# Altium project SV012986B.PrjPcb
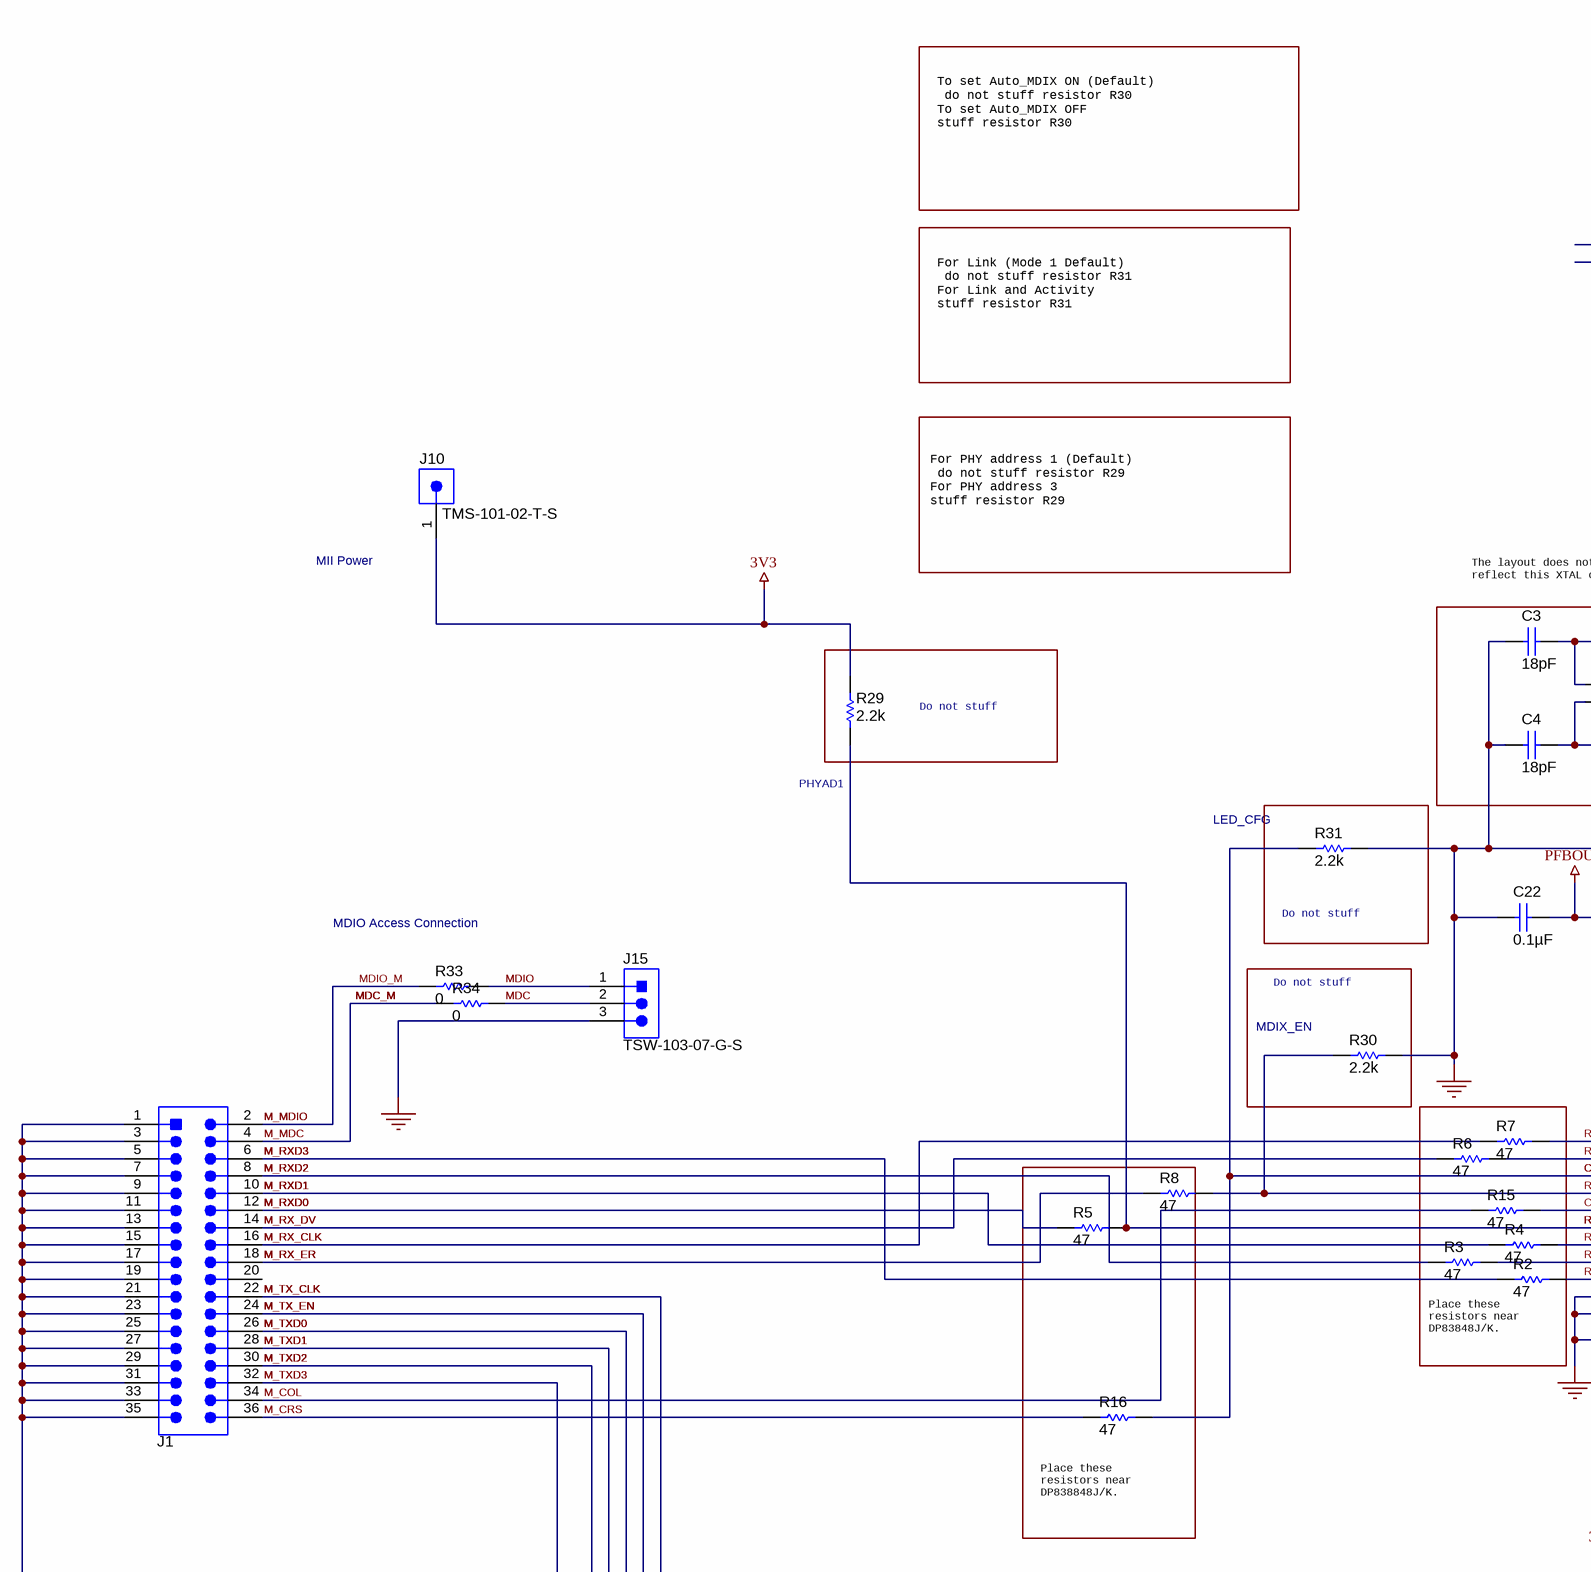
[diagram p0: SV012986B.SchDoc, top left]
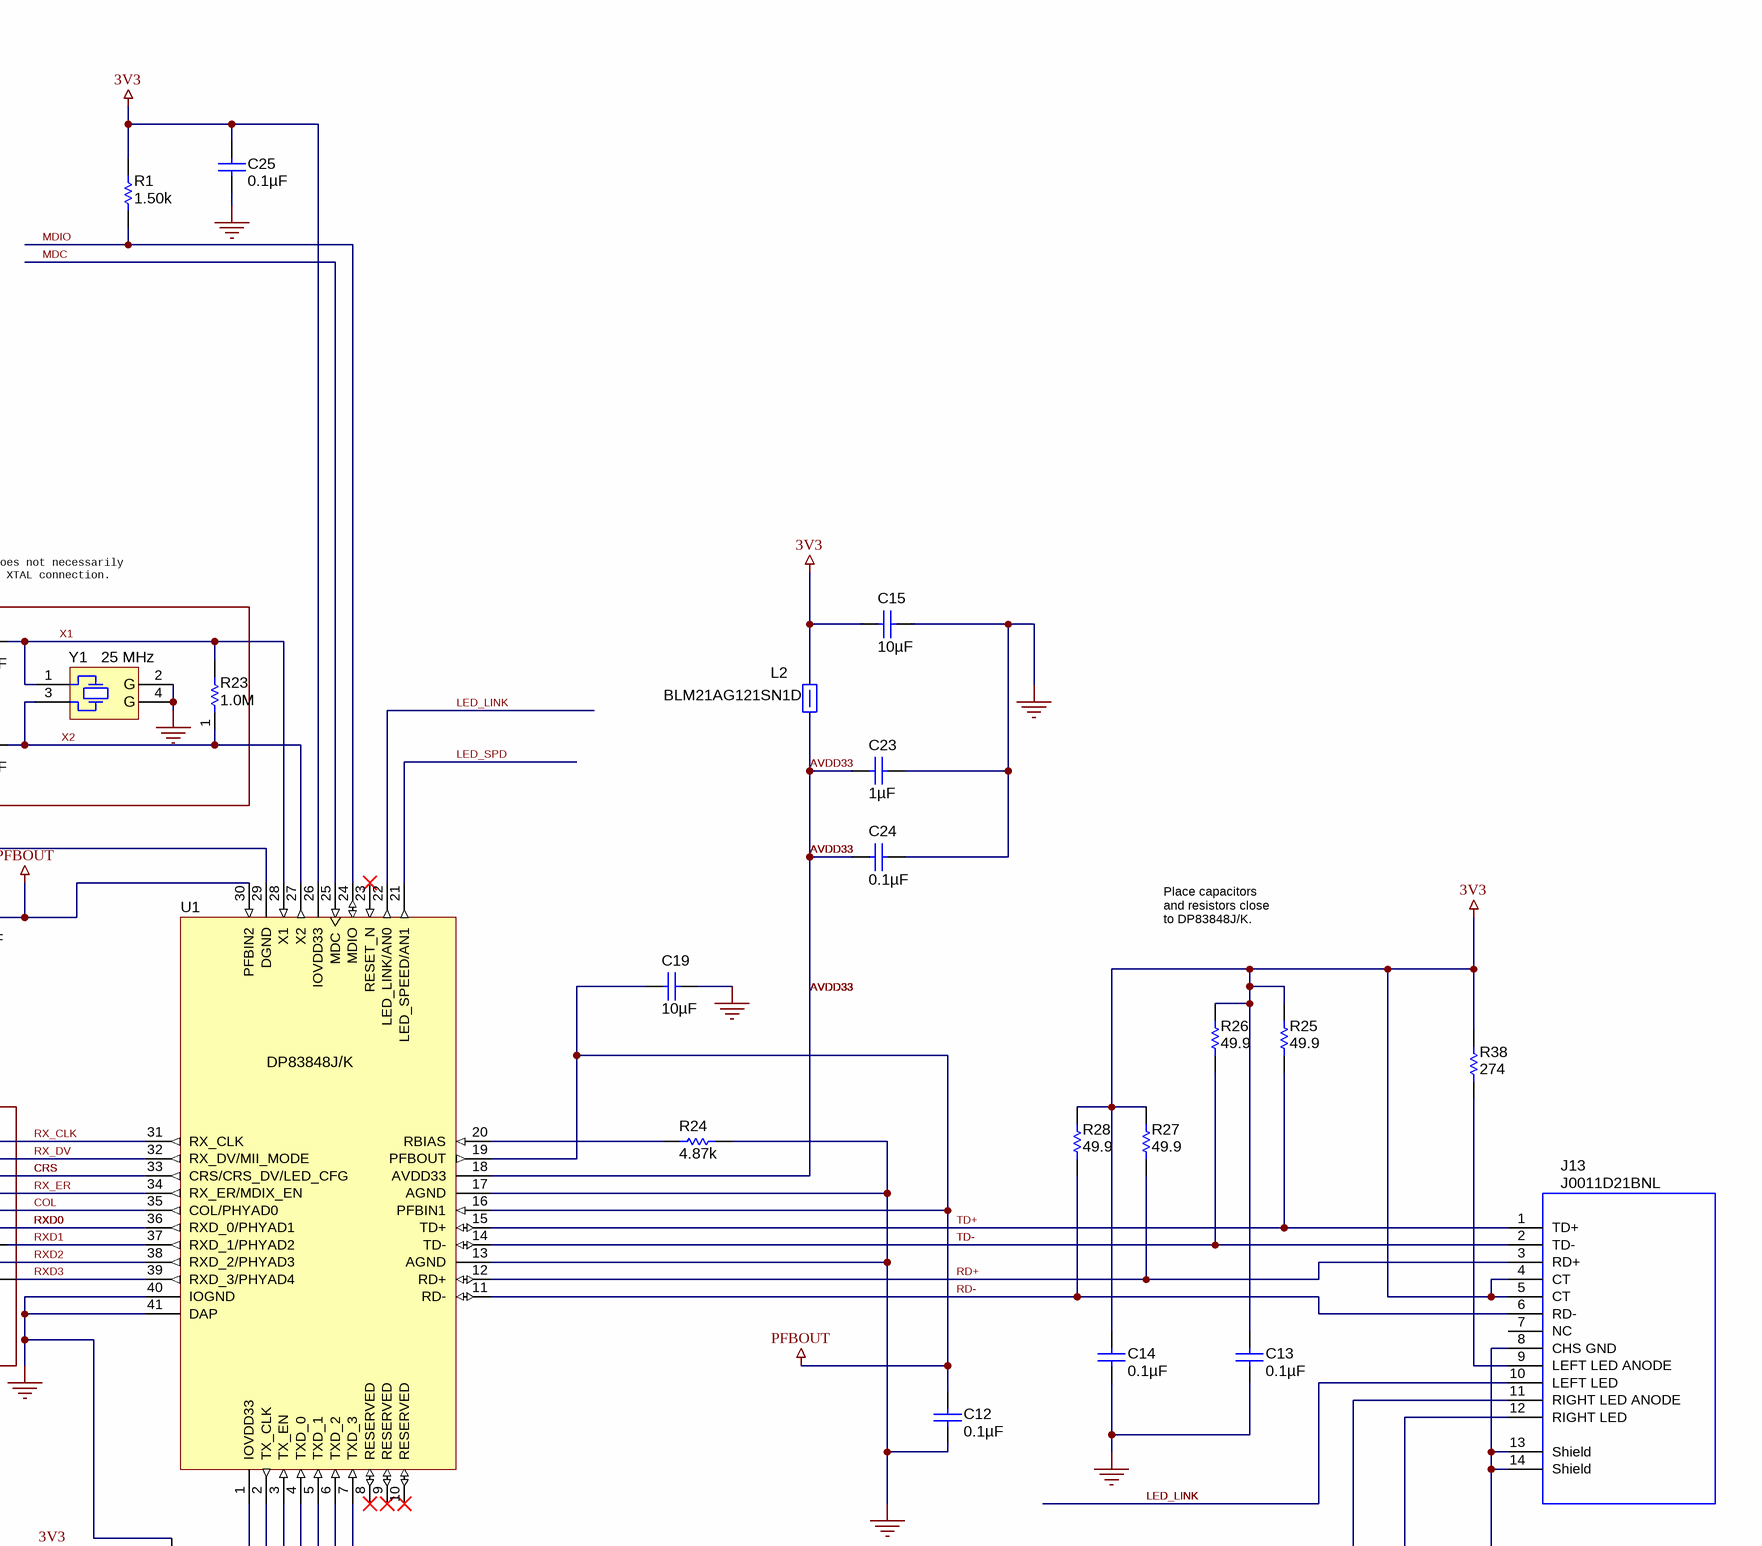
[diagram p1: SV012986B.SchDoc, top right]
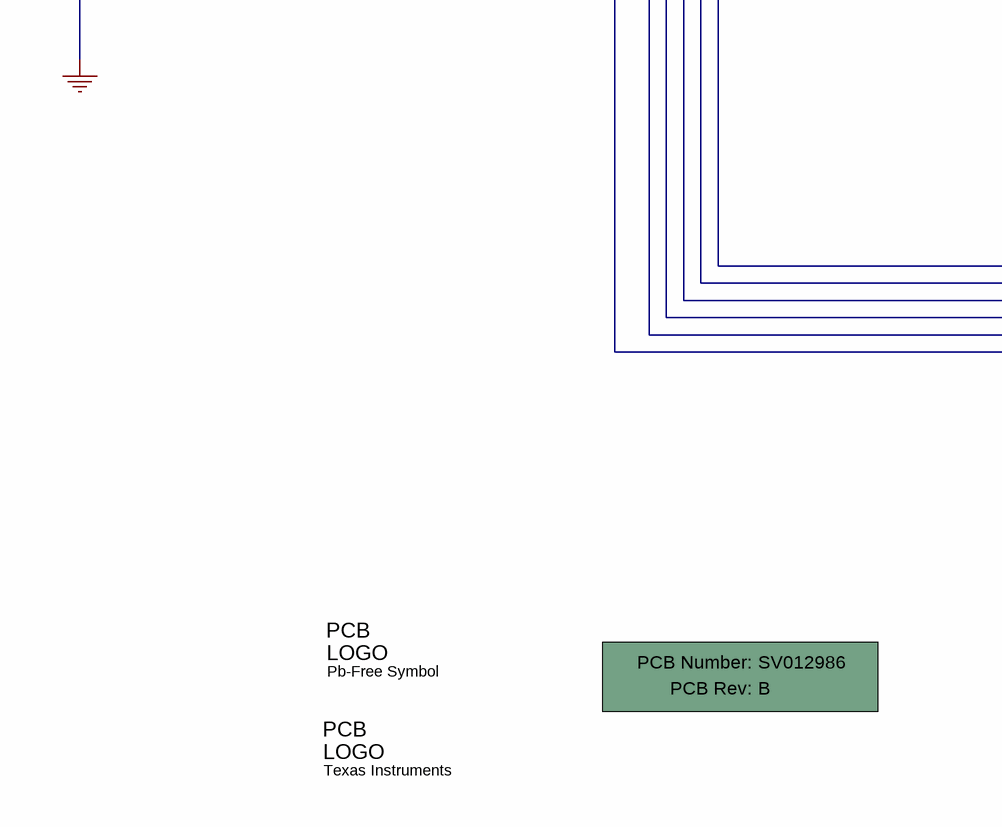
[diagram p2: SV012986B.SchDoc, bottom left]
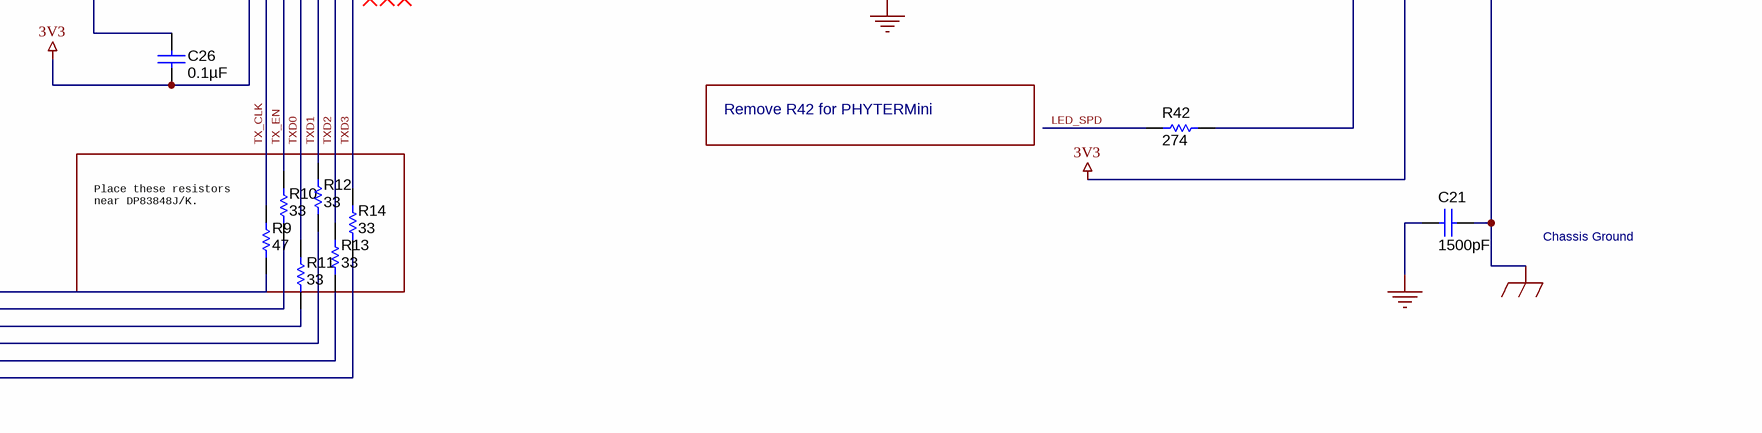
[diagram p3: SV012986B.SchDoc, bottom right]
CopyrightYear: 2014; EVM_Orderable: DP83848K-MAU-EK; PCB_Layout: SVTronics; PCB_Rev: B; PRJ_Customer: Public Release; PRJ_Engineer: Matt Dillingham; PRJ_Number: SV012986; PRJ_Title: DP83848K-MAU-EK; SCH_Rev: B; TechSupport: http://www.ti.com/support; TID: n/a
1 sheet, 52 parts. Net scope: global (net labels, ports and power ports of the same name join across sheets).
Board file: SV012986B.PCBDOC

## Sheet SV012986B.SchDoc
size 558 x 431 mm; Date: Not shown in title block; ApprovedBy: Not shown in title block; CheckedBy: Not shown in title block; Author: Not shown in title block; CompanyName: Not shown in title block; Engineer: Not shown in title block; Organization: Not shown in title block; Address1: Not shown in title block; Address2: Not shown in title block; Address3: Not shown in title block; Address4: Not shown in title block; DocumentNumber: 1; Revision: Use project parameter SCH_Rev; SheetNumber: 2; SheetTotal: 3; PageSetup: Record=PageOptions¦CenterHorizontal=True¦CenterVertical=True¦PrintScale=1.00¦XCorrection=1.00¦YCorrection=1.00¦PrintKind=0¦BorderSize=5000000¦LeftOffset=0¦BottomOffset=0¦Orientation=2¦PaperLength=1000¦PaperWidth=1000¦Scale=100¦PaperSource=15¦PrintQuality=600¦MediaType=1¦DitherType=10¦PaperKind=Letter¦PrintScaleMode=1

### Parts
!PCB  Printed Circuit Board  (value not drawn)  (mechanical)
C3  ValueDisplayed: 18pF  [0603]  (hidden comment: GRM1885C1H180JA01D)
C4  ValueDisplayed: 18pF  [0603]  (hidden comment: GRM1885C1H180JA01D)
C12  ValueDisplayed: 0.1µF  [0603]  (hidden comment: GRM188R61C104KA01D)
C13  ValueDisplayed: 0.1µF  [0603]  (hidden comment: GRM188R61C104KA01D)
C14  ValueDisplayed: 0.1µF  [0603]  (hidden comment: GRM188R61C104KA01D)
C15  ValueDisplayed: 10µF  [0805L]  (hidden comment: C0805C106M8PACTU)
C19  ValueDisplayed: 10µF  [0805_HV]  (hidden comment: C0805C106M8PACTU)
C21  ValueDisplayed: 1500pF  [1808]  (hidden comment: GR442QR73D152KW01L)
C22  ValueDisplayed: 0.1µF  [0603]  (hidden comment: GRM188R61C104KA01D)
C23  ValueDisplayed: 1µF  [0805_HV]  (hidden comment: GRM216R61A105KA01D)
C24  ValueDisplayed: 0.1µF  [0603]  (hidden comment: GRM188R61C104KA01D)
C25  ValueDisplayed: 0.1µF  [0603]  (hidden comment: GRM188R61C104KA01D)
C26  ValueDisplayed: 0.1µF  [0603]  (hidden comment: GRM188R61C104KA01D)
J1  TSW-118-07-G-D  [TSW-118-07-G-D]  (value not drawn)
J10  TMS-101-02-T-S  [SAMTEC_TMS-101-02-T-S]
J13  J0011D21BNL  [Pulse_J0011D21BNL]
J15  TSW-103-07-G-S  [TSW-103-07-G-S]
L2  BLM21AG121SN1D  [0805_HV]
Logo1  Pb-Free Symbol  [Pb-Free_Overlay_Small]  (no BOM)
Logo2  Texas Instruments  [TI_Symbol_Overlay_Small]  (no BOM)
R1  ValueDisplayed: 1.50k  [0402L]  (hidden comment: CRCW04021K50FKED)
R2  ValueDisplayed: 47  [0402]  (hidden comment: CRCW040247R0JNED)
R3  ValueDisplayed: 47  [0402]  (hidden comment: CRCW040247R0JNED)
R4  ValueDisplayed: 47  [0402]  (hidden comment: CRCW040247R0JNED)
R5  ValueDisplayed: 47  [0402L]  (hidden comment: CRCW040247R0JNED)
R6  ValueDisplayed: 47  [0402]  (hidden comment: CRCW040247R0JNED)
R7  ValueDisplayed: 47  [0402]  (hidden comment: CRCW040247R0JNED)
R8  ValueDisplayed: 47  [0402L]  (hidden comment: CRCW040247R0JNED)
R9  ValueDisplayed: 47  [0402]  (hidden comment: CRCW040247R0JNED)
R10  ValueDisplayed: 33  [0402]  (hidden comment: CRCW040233R0JNED)
R11  ValueDisplayed: 33  [0402L]  (hidden comment: CRCW040233R0JNED)
R12  ValueDisplayed: 33  [0402]  (hidden comment: CRCW040233R0JNED)
R13  ValueDisplayed: 33  [0402]  (hidden comment: CRCW040233R0JNED)
R14  ValueDisplayed: 33  [0402]  (hidden comment: CRCW040233R0JNED)
R15  ValueDisplayed: 47  [0402]  (hidden comment: CRCW040247R0JNED)
R16  ValueDisplayed: 47  [0402]  (hidden comment: CRCW040247R0JNED)
R23  ValueDisplayed: 1.0M  [0402]  (hidden comment: CRCW04021M00JNED)
R24  ValueDisplayed: 4.87k  [0402L]  (hidden comment: CRCW04024K87FKED)
R25  ValueDisplayed: 49.9  [0603]  (hidden comment: CRCW060349R9FKEA)
R26  ValueDisplayed: 49.9  [0603]  (hidden comment: CRCW060349R9FKEA)
R27  ValueDisplayed: 49.9  [0603]  (hidden comment: CRCW060349R9FKEA)
R28  ValueDisplayed: 49.9  [0603]  (hidden comment: CRCW060349R9FKEA)
R29  ValueDisplayed: 2.2k  [0402L]  (hidden comment: CRCW04022K20JNED)
R30  ValueDisplayed: 2.2k  [0402L]  (hidden comment: CRCW04022K20JNED)
R31  ValueDisplayed: 2.2k  [0402]  (hidden comment: CRCW04022K20JNED)
R33  ValueDisplayed: 0  [0402]  (hidden comment: CRCW04020000Z0ED)
R34  ValueDisplayed: 0  [0402]  (hidden comment: CRCW04020000Z0ED)
R38  ValueDisplayed: 274  [0402]  (hidden comment: CRCW0402274RFKED)
R42  ValueDisplayed: 274  [0402S]  (hidden comment: CRCW0402274RFKED)
U1  DP83848J/K  [SQA40B]
Y1  Frequency: 25 MHz  [Ecliptek_EA5070]  (hidden comment: EA5070PA18-25.000M)

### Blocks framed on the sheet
Do not stuff: R29
Do not stuff: R31
MDIX_EN: R30

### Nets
3V3: C13.1 C14.1 C15.2 C25.1 C26.2 J10.1 J13.4(CT) J13.5(CT) J13.12(RIGHT_LED) L2.2 R1.2 R25.2 R26.2 R27.2 R28.2 R29.2 R38.2 U1.1(IOVDD33) U1.26(IOVDD33)
GND: C3.2 C4.2 C12.2 C13.2 C14.2 C15.1 C19.1 C21.2 C22.2 C23.1 C24.1 C25.2 C26.1 J1.1 J1.3 J1.5 J1.7 J1.9 J1.11 J1.13 J1.15 J1.17 J1.19 J1.21 J1.23 J1.25 J1.27 J1.29 J1.31 J1.33 J1.35 J15.3 R24.2 R30.1 R31.2 U1.13(AGND) U1.17(AGND) U1.29(DGND) U1.40(IOGND) U1.41(DAP) Y1.2(GND) Y1.4(GND)
GND_Chassis: C21.1 J13.8(CHS_GND) J13.13(Shield) J13.14(Shield)
PFBOUT: C12.1 C19.2 C22.1 U1.16(PFBIN1) U1.19(PFBOUT) U1.30(PFBIN2)
AVDD33: C23.2 C24.2 L2.1 U1.18(AVDD33)
COL: R15.2 U1.35(COL/PHYAD0)
CRS: R16.2 R31.1 U1.33(CRS/CRS_DV/LED_CFG)
LED_LINK: J13.10(LEFT_LED) U1.22(LED_LINK/AN0)
LED_SPD: R42.1 U1.21(LED_SPEED/AN1)
M_COL: J1.34 R15.1
M_CRS: J1.36 R16.1
M_MDC: J1.4 R34.1  [also labelled MDC_M]
M_MDIO: J1.2 R33.1  [also labelled MDIO_M]
M_RX_CLK: J1.16 R7.1
M_RX_DV: J1.14 R6.1
M_RX_ER: J1.18 R8.1
M_RXD0: J1.12 R5.1
M_RXD1: J1.10 R4.1
M_RXD2: J1.8 R3.1
M_RXD3: J1.6 R2.1
M_TX_CLK: J1.22 R9.1
M_TX_EN: J1.24 R10.1
M_TXD0: J1.26 R11.1
M_TXD1: J1.28 R12.1
M_TXD2: J1.30 R13.1
M_TXD3: J1.32 R14.1
MDC: J15.2 R34.2 U1.25(MDC)
MDIO: J15.1 R1.1 R33.2 U1.24(MDIO)
RD+: J13.3(RD+) R27.1 U1.12(RD+)
RD-: J13.6(RD-) R28.1 U1.11(RD-)
RX_CLK: R7.2 U1.31(RX_CLK)
RX_DV: R6.2 U1.32(RX_DV/MII_MODE)
RX_ER: R8.2 R30.2 U1.34(RX_ER/MDIX_EN)
RXD0: R5.2 R29.1 U1.36(RXD_0/PHYAD1)
RXD1: R4.2 U1.37(RXD_1/PHYAD2)
RXD2: R3.2 U1.38(RXD_2/PHYAD3)
RXD3: R2.2 U1.39(RXD_3/PHYAD4)
TD+: J13.1(TD+) R25.1 U1.15(TD+)
TD-: J13.2(TD-) R26.1 U1.14(TD-)
TX_CLK: R9.2 U1.2(TX_CLK)
TX_EN: R10.2 U1.3(TX_EN)
TXD0: R11.2 U1.4(TXD_0)
TXD1: R12.2 U1.5(TXD_1)
TXD2: R13.2 U1.6(TXD_2)
TXD3: R14.2 U1.7(TXD_3)
X1: C3.1 R23.2 U1.28(X1) Y1.1
X2: C4.1 R23.1 U1.27(X2) Y1.3
NetJ13_9: J13.9(LEFT_LED_ANODE) R38.1
NetJ13_11: J13.11(RIGHT_LED_ANODE) R42.2
NetR24_1: R24.1 U1.20(RBIAS)

Not connected (* = marked no-connect by the designer): J1 20; J13 7(NC); U1 8(RESERVED)* 9(RESERVED)* 10(RESERVED)* 23(RESET_N)*

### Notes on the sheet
- To set Auto_MDIX ON (Default)
  do not stuff resistor R30
  To set Auto_MDIX OFF
  stuff resistor R30
- For Link (Mode 1 Default)
  do not stuff resistor R31
  For Link and Activity
  stuff resistor R31
- MII Power
- For PHY address 1 (Default)
  do not stuff resistor R29
  For PHY address 3
  stuff resistor R29
- (near C3) The layout does not necessarily
  reflect this XTAL connection.
- (near R29) PHYAD1
- (near R31) LED_CFG
- MDIO Access Connection
- (near R30) Do not stuff
- Place capacitors
  and resistors close
  to DP83848J/K.
- (near R2) Place these
  resistors near
  DP83848J/K.
- (near R16) Place these
  resistors near
  DP838848J/K.
- Remove R42 for PHYTERMini
- Place these resistors
  near DP83848J/K.
- Chassis Ground

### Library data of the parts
!PCB = PCB: Manufacturer: Any; PartNumber: SV012986; SymbolCreator: a0412235
C3 C4 = GRM1885C1H180JA01D: CAP, CERM, 18 pF, 50 V, +/- 5%, C0G/NP0, 0603; Manufacturer: MuRata; Polarized: N; CompType: Capacitor; Value: 18pF; U/M: EA; Cap_F: 0.000000000018; Tolerance_%: 5; Value1: Unknown; VDC_V: 50; Value2: 50V; TaMin_C: -55; TaMax_C: 125
C12-C14 C22 C24-C26 = GRM188R61C104KA01D: CAP, CERM, 0.1 µF, 16 V, +/- 10%, X5R, 0603; Manufacturer: MuRata; Polarized: N; CompType: Capacitor; Value: 0.1uF; U/M: EA; Cap_F: 0.0000001; Tolerance_%: 10; Value1: Unknown; VDC_V: 16; Value2: 16V; TaMin_C: -55; TaMax_C: 85
C15 C19 = C0805C106M8PACTU: CAP, CERM, 10 µF, 10 V, +/- 20%, X5R, 0805; Manufacturer: Kemet; Polarized: N; CompType: Capacitor; Value: 10uF; U/M: EA; Cap_F: 0.00001; Tolerance_%: 20; ESR_ohm: 0.003; Value1: 0.003 ohm; VDC_V: 10; Value2: 10V; IRMS_A: 11.43; TaMin_C: -55; TaMax_C: 85; Cap_Case: 0805
C21 = GR442QR73D152KW01L: CAP, CERM, 1500 pF, 2000 V, +/- 10%, X7R, 1808; Manufacturer: MuRata; Polarized: N; CompType: Capacitor; Value: 1500pF; U/M: EA; Cap_F: 0.0000000015; Tolerance_%: 10; Value1: Unknown; VDC_V: 2000; Value2: 2000V; TaMin_C: -55; TaMax_C: 125
C23 = GRM216R61A105KA01D: CAP, CERM, 1 µF, 10 V, +/- 10%, X5R, 0805; Manufacturer: MuRata; Polarized: N; CompType: Capacitor; Value: 1uF; U/M: EA; Cap_F: 0.000001; Tolerance_%: 10; Value1: Unknown; Value2: 10V; TaMin_C: -55; TaMax_C: 85; Cap_Case: 0805
J1 = TSW-118-07-G-D: Header, 100mil, 18x2, Gold, TH; Manufacturer: Samtec; SymbolCreator: a0411947; U/M: EA
J10 = TMS-101-02-T-S: Header, 1x1, Tin, TH; Manufacturer: Samtec; SymbolCreator: a0412235; U/M: EA
J13 = J0011D21BNL: Connector, RJ-45 with integrated magnetics, 1x1, Gold, R/A, TH; Manufacturer: Pulse Engineering; SymbolCreator: Altium; U/M: EA
J15 = TSW-103-07-G-S: Header, 100mil, 3x1, Gold, TH; Manufacturer: Samtec; SymbolCreator: a0799628; U/M: EA
L2 = BLM21AG121SN1D: Ferrite Bead, 120 ohm @ 100 MHz, 0.8 A, 0805; Manufacturer: MuRata; Value: 120 ohm; Imax_A: 0.8; DCR_ohm: 0.1; Value1: 0.1 ohm; Value2: 0.8A; ZTyp@100MHz_Ohm: 120
Logo1 = Pb-Free: SymbolCreator: a0412235
Logo2 = TI_Logo: Texas Instrument Corporate Signature; SymbolCreator: a0412235
R1 = CRCW04021K50FKED: RES, 1.50 k, 1%, 0.063 W, 0402; Manufacturer: Vishay-Dale; CompType: Resistor; Value: 1.50k; Res_ohm: 1500; Value_Code: 1k50; Tolerance_%: 1; Power_W: 0.063; Value2: 0.063W; VDC_V: 50; TempCo: 100 ppm/C; EIA_Code: E96; U/M: EA
R2-R9 R15 R16 = CRCW040247R0JNED: RES, 47, 5%, 0.063 W, 0402; Manufacturer: Vishay-Dale; CompType: Resistor; Value: 47; Value_Code: 47R0; Tolerance_%: 5; Power_W: 0.063; Value2: 0.063W; VDC_V: 50; TempCo: 200 ppm/C; EIA_Code: E24; U/M: EA
R10-R14 = CRCW040233R0JNED: RES, 33, 5%, 0.063 W, 0402; Manufacturer: Vishay-Dale; CompType: Resistor; Value: 33; Value_Code: 33R0; Tolerance_%: 5; Power_W: 0.063; Value2: 0.063W; VDC_V: 50; TempCo: 200 ppm/C; EIA_Code: E24; U/M: EA
R23 = CRCW04021M00JNED: RES, 1.0 M, 5%, 0.063 W, 0402; Manufacturer: Vishay-Dale; CompType: Resistor; Value: 1.0Meg; Res_ohm: 1000000; Value_Code: 1M00; Tolerance_%: 5; Power_W: 0.063; Value2: 0.063W; VDC_V: 50; TempCo: 200 ppm/C; EIA_Code: E24; U/M: EA
R24 = CRCW04024K87FKED: RES, 4.87 k, 1%, 0.063 W, 0402; Manufacturer: Vishay-Dale; CompType: Resistor; Value: 4.87k; Res_ohm: 4870; Value_Code: 4k87; Tolerance_%: 1; Power_W: 0.063; Value2: 0.063W; VDC_V: 50; TempCo: 100 ppm/C; EIA_Code: E96; U/M: EA
R25-R28 = CRCW060349R9FKEA: RES, 49.9, 1%, 0.1 W, 0603; Manufacturer: Vishay-Dale; CompType: Resistor; Value: 49.9; Value_Code: 49R9; Tolerance_%: 1; Power_W: 0.1; Value2: 0.1W; VDC_V: 75; TempCo: 100 ppm/C; EIA_Code: E96; U/M: EA
R29-R31 = CRCW04022K20JNED: RES, 2.2 k, 5%, 0.063 W, 0402; Manufacturer: Vishay-Dale; CompType: Resistor; Value: 2.2k; Res_ohm: 2200; Value_Code: 2k20; Tolerance_%: 5; Power_W: 0.063; Value2: 0.063W; VDC_V: 50; TempCo: 200 ppm/C; EIA_Code: E24; U/M: EA
R33 R34 = CRCW04020000Z0ED: RES, 0, 5%, 0.063 W, 0402; Manufacturer: Vishay-Dale; CompType: Resistor; Value: 0; Value_Code: 0000; Tolerance_%: 5; Power_W: 0.063; Value2: 0.063W; VDC_V: 50; TempCo: 200 ppm/C; EIA_Code: E24; U/M: EA
R38 R42 = CRCW0402274RFKED: RES, 274, 1%, 0.063 W, 0402; Manufacturer: Vishay-Dale; CompType: Resistor; Value: 274; Value_Code: 274R; Tolerance_%: 1; Power_W: 0.063; Value2: 0.063W; VDC_V: 50; TempCo: 100 ppm/C; EIA_Code: E96; U/M: EA
U1 = DP83848JSQ: PHYTER® Mini LS Commercial Temperature Single Port 10/100 Mb/s Ethernet Transceiver, 40-pin LLP; Manufacturer: Texas Instruments; PackageTopMarking: NS*UZXYTT*83848JSQ; PowerWise: N; CompType: Interface IC
Y1 = EA5070PA18-25.000M: Quartz Crystal Resonator, 25 MHz, SMD; Manufacturer: Ecliptek; SymbolCreator: a0412235; U/M: EA; TaMin_C: -20; TaMax_C: 70; Frequency Stability: ±10ppm

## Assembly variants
002: not fitted R29 R30 R31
